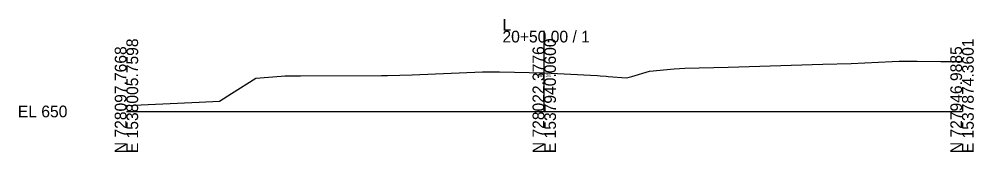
# Model space of a CAD drawing. Extents: x -26 to 1203, y -10 to 9522.
# Drawn here: x 974.3 to 1202.8, y 1990.3 to 2022.1 of the extents above; entities that cross this region are included whole.
import ezdxf

# ---------------------------------------------------------------- set-up
doc = ezdxf.new("R2010")
doc.units = 0
for name, color, linetype in [('Default', 7, 'Continuous'), ('Exist Cross Section Cell', 7, 'Continuous'), ('Exist XS Center Line Elevation Label', 7, 'Continuous'), ('Exist XS Ground Line', 7, 'Continuous')]:
    doc.layers.add(name, color=color, linetype=linetype)

msp = doc.modelspace()

# ---------------------------------------------------------------- linework, layer by layer
at = {"layer": 'Exist Cross Section Cell'}
for p, q in [((1100, 2000), (1100, 2019.33)), ((1000, 2000), (1100, 2000)), ((1100, 2000), (1200, 2000))]:
    msp.add_line(p, q, dxfattribs=at)
at = {"layer": 'Exist XS Ground Line'}
msp.add_lwpolyline([(1000, 2001.44), (1017.38, 2002.26), (1022.27, 2002.49), (1025.16, 2004.3), (1030.95, 2007.97), (1037.04, 2008.45), (1037.9, 2008.52), (1041.65, 2008.54), (1061.05, 2008.59), (1062.52, 2008.62), (1068.42, 2008.81), (1085.2, 2009.46), (1087.29, 2009.51), (1089.3, 2009.46), (1100, 2009.26), (1100.07, 2009.26), (1111.1, 2008.67), (1112.76, 2008.58), (1113.38, 2008.57), (1114.81, 2008.42), (1115.31, 2008.39), (1119.71, 2008.05), (1120.99, 2008.41), (1125.19, 2009.65), (1131.13, 2010.23), (1133.68, 2010.34), (1143.99, 2010.64), (1166.68, 2011.31), (1173.47, 2011.49), (1183.28, 2011.98), (1184.95, 2012.05), (1189.22, 2012.07), (1194.9, 2011.98), (1200, 2011.97)], dxfattribs=at)

# ---------------------------------------------------------------- texts
at = {"layer": 'Default'}
msp.add_text('-', height=0.0001, dxfattribs=at).set_placement((1000, 2000))
msp.add_text('-', height=0.0001, dxfattribs=at).set_placement((1000, 2000))
msp.add_text('-', height=0.0001, dxfattribs=at).set_placement((1000, 2000))
at = {"layer": 'Exist Cross Section Cell'}
for s, p in [('L', (1090, 2019.33)), ('20+50.00 / 1', (1090, 2016.53)), ('EL 650', (974, 1998.6))]:
    msp.add_text(s, height=2.8, dxfattribs=at).set_placement(p)
for s, p in [('E 1538005.7598', (1002.8, 1990)), ('E 1537940.0600', (1102.8, 1990)), ('E 1537874.3601', (1202.8, 1990)), ('N 728097.7668', (1000, 1990)), ('N 728022.3776', (1100, 1990)), ('N 727946.9885', (1200, 1990))]:
    msp.add_text(s, height=2.8, rotation=90, dxfattribs=at).set_placement(p)
at = {"layer": 'Exist XS Center Line Elevation Label'}
msp.add_text('659.26', height=0.75, dxfattribs=at).set_placement((1098.38, 2008.23))

doc.saveas('drawing.dxf')
